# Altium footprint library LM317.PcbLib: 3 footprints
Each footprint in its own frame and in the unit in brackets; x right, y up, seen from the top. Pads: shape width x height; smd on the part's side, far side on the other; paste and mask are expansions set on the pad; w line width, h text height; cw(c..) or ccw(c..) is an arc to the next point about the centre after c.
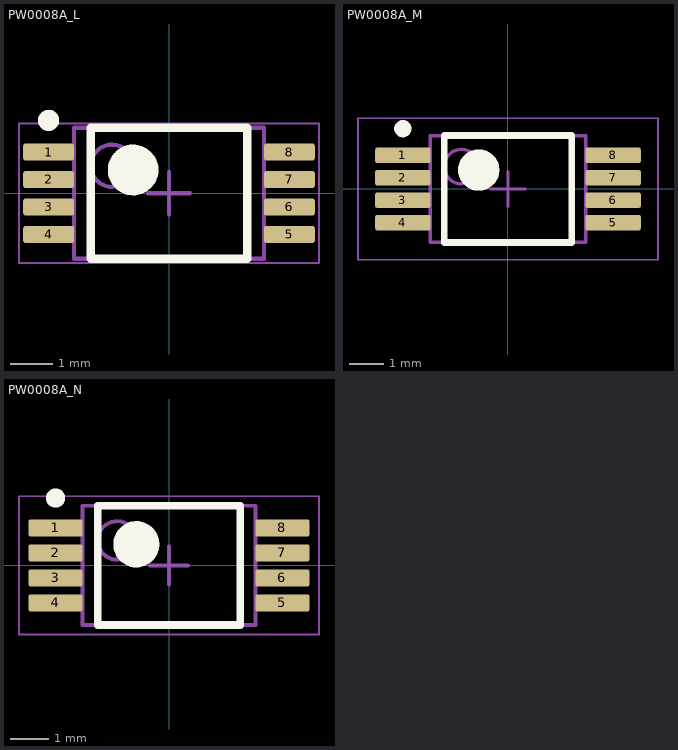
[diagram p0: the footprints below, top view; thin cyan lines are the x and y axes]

## PW0008A_L [mm] "SOP, 8-Leads, Body 4.5x3.1mm, Pitch 0.65mm, IPC High Density"
height 1.2
pads (8):
  rrect25% 1.2x0.4 smd: 1(-2.85,0.975) 2(-2.85,0.325) 3(-2.85,-0.325) 4(-2.85,-0.975) 5(2.85,-0.975) 6(2.85,-0.325) 7(2.85,0.325) 8(2.85,0.975)
Top Overlay:
  circle w0.25: c-2.85,1.725 r0.125
  circle w0.6: c-0.85,0.55 r0.3
  lines w0.2: -1.85,-1.55 -1.85,1.55 1.85,1.55 1.85,-1.55 -1.85,-1.55
Mechanical 1:
  text ".Designator" at -1.524,-0.635 h0.8
Mechanical 13:
  circle w0.1: c-1.35,0.65 r0.5
  lines w0.1: -2.25,-1.55 -2.25,1.55 2.25,1.55 2.25,-1.55 -2.25,-1.55
Mechanical 15:
  lines w0.05: -3.55,-1.65 -3.55,1.65 3.55,1.65 3.55,-1.65 -3.55,-1.65
  lines w0.1: -0.5,0 0.5,0 ; 0,-0.5 0,0.5
3D body "TSSOP-8.stp": height 1.2, standoff 0, extent -3.228,-1.5 3.228,1.5

## PW0008A_M [mm] "SOP, 8-Leads, Body 4.5x3.1mm, Pitch 0.65mm, IPC Low Density"
height 1.2
pads (8):
  rrect22% 1.6x0.45 smd: 1(-3.05,0.975) 2(-3.05,0.325) 3(-3.05,-0.325) 4(-3.05,-0.975) 5(3.05,-0.975) 6(3.05,-0.325) 7(3.05,0.325) 8(3.05,0.975)
Top Overlay:
  circle w0.25: c-3.05,1.75 r0.125
  circle w0.6: c-0.85,0.55 r0.3
  lines w0.2: -1.85,-1.55 -1.85,1.55 1.85,1.55 1.85,-1.55 -1.85,-1.55
Mechanical 1:
  text ".Designator" at -1.524,-0.508 h1.02
Mechanical 13:
  circle w0.1: c-1.35,0.65 r0.5
  lines w0.1: -2.25,-1.55 -2.25,1.55 2.25,1.55 2.25,-1.55 -2.25,-1.55
Mechanical 15:
  lines w0.05: -4.35,-2.05 -4.35,2.05 4.35,2.05 4.35,-2.05 -4.35,-2.05
  lines w0.1: -0.5,0 0.5,0 ; 0,-0.5 0,0.5
3D body "TSSOP-8.stp": height 1.2, standoff 0, extent -3.228,-1.5 3.228,1.5

## PW0008A_N [mm] "SOP, 8-Leads, Body 4.5x3.1mm, Pitch 0.65mm, IPC Medium Density"
height 1.2
pads (8):
  rrect22% 1.4x0.45 smd: 1(-2.95,0.975) 2(-2.95,0.325) 3(-2.95,-0.325) 4(-2.95,-0.975) 5(2.95,-0.975) 6(2.95,-0.325) 7(2.95,0.325) 8(2.95,0.975)
Top Overlay:
  circle w0.6: c-0.85,0.55 r0.3
  circle w0.25: c-2.95,1.75 r0.125
  lines w0.2: -1.85,-1.55 1.85,-1.55 1.85,1.55 -1.85,1.55 -1.85,-1.55
Mechanical 1:
  text ".Designator" at -1.524,-0.508 h1.02
Mechanical 13:
  circle w0.1: c-1.35,0.65 r0.5
  lines w0.1: -2.25,-1.55 2.25,-1.55 2.25,1.55 -2.25,1.55 -2.25,-1.55
Mechanical 15:
  lines w0.05: -3.9,-1.8 3.9,-1.8 3.9,1.8 -3.9,1.8 -3.9,-1.8
  lines w0.1: -0.5,0 0.5,0 ; 0,-0.5 0,0.5
3D body "TSSOP-8.stp": height 1.2, standoff 0, extent -3.228,-1.5 3.228,1.5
